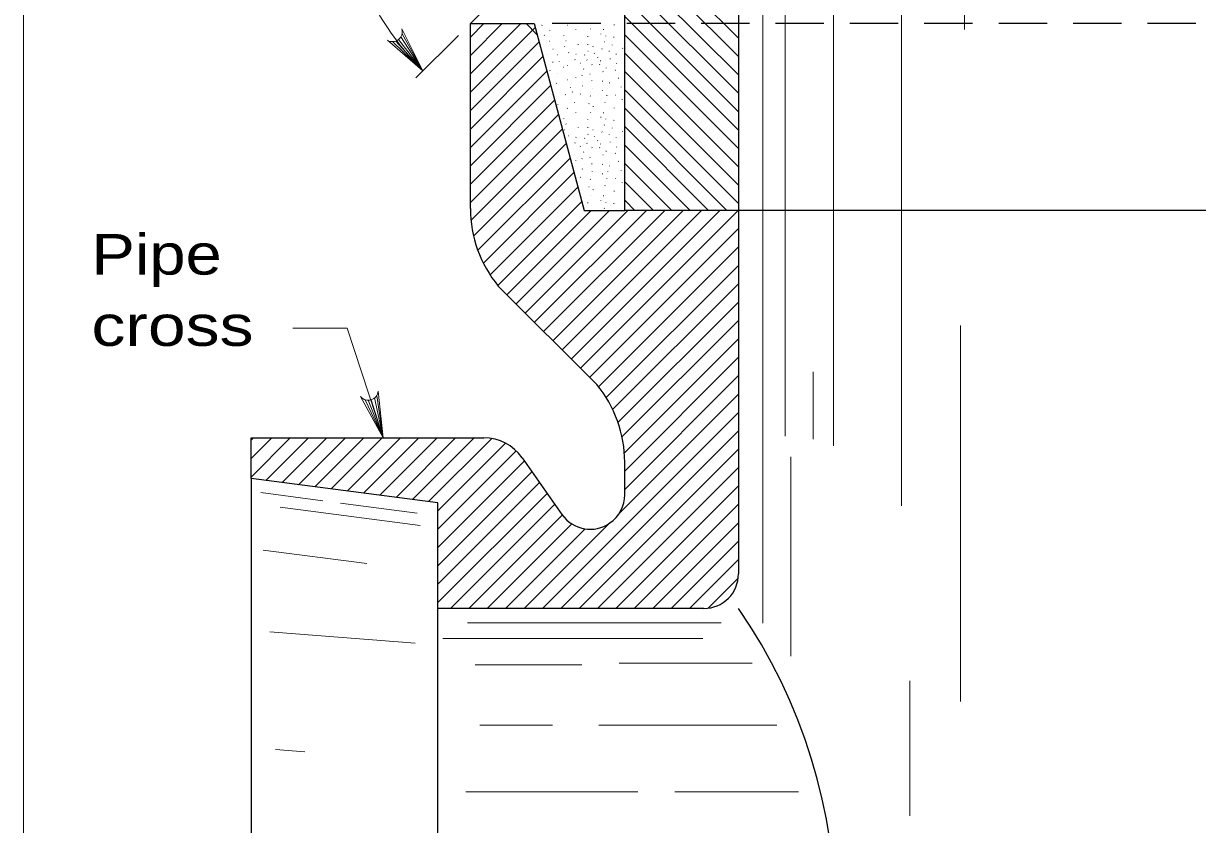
# Model space of a CAD drawing. Extents: x 1302.9 to 1336.9, y 688.5 to 710.5.
# Drawn here: x 1314.494 to 1319.007, y 697.687 to 700.767 of the extents above; entities that cross this region are included whole.
import ezdxf

# ---------------------------------------------------------------- set-up
doc = ezdxf.new("R2010")
doc.units = 0
doc.header["$LTSCALE"] = 0.062
doc.linetypes.add('MEDIUM_DASHED', pattern=[4.5, 3, -1.5])
doc.layers.add('1', color=7, linetype='Continuous', lineweight=13)

msp = doc.modelspace()

# ---------------------------------------------------------------- linework, layer by layer
at = {"layer": '1'}
for p, q in [((1314.49383, 700.27), (1314.49383, 706.63708)), ((1317.33667, 698.46067), (1317.33667, 702.85392)), ((1317.60758, 699.14283), (1317.60758, 702.36408)), ((1317.42233, 702.01592), (1317.42233, 699.18083)), ((1318.11208, 701.78092), (1318.11208, 700.74375)), ((1317.24267, 700.71042), (1316.80542, 701.14767)), ((1317.86967, 698.91258), (1317.86967, 701.1255)), ((1317.24267, 700.63975), (1316.80542, 701.077)), ((1317.24267, 700.56908), (1316.80542, 701.00633)), ((1317.24267, 700.49842), (1316.80542, 700.93567)), ((1317.24267, 700.42775), (1316.80542, 700.865)), ((1317.24267, 700.35708), (1316.80542, 700.79433)), ((1316.21192, 700.71442), (1316.26408, 700.76658)), ((1316.21192, 700.64375), (1316.33475, 700.76658)), ((1316.21192, 700.57308), (1316.40542, 700.76658)), ((1316.21192, 700.50242), (1316.46075, 700.75125)), ((1316.46792, 700.7245), (1316.42583, 700.76658)), ((1316.46792, 700.7245), (1316.42583, 700.76658)), ((1316.48725, 700.75908), (1316.48817, 700.75992)), ((1316.58375, 700.76092), (1316.5855, 700.7605)), ((1316.61675, 700.74367), (1316.61758, 700.7445)), ((1316.67317, 700.74492), (1316.674, 700.74575)), ((1316.723, 700.74383), (1316.72475, 700.7435)), ((1316.765, 700.761), (1316.7645, 700.76267)), ((1315.91342, 700.69692), (1316.02975, 700.5845)), ((1315.9255, 700.6995), (1316.02975, 700.5845)), ((1315.9355, 700.70517), (1316.02975, 700.5845)), ((1315.94508, 700.71625), (1316.02975, 700.5845)), ((1315.9495, 700.7275), (1316.02975, 700.5845)), ((1316.16608, 700.72075), (1316.00283, 700.5575)), ((1316.21192, 700.43175), (1316.47575, 700.69558)), ((1316.49633, 700.72075), (1316.49575, 700.72242)), ((1316.5155, 700.69908), (1316.51725, 700.69867)), ((1316.518, 700.73858), (1316.51742, 700.74025)), ((1316.5715, 700.72075), (1316.57092, 700.72242)), ((1316.57833, 700.7005), (1316.58008, 700.70017)), ((1316.66383, 700.71608), (1316.66317, 700.71775)), ((1316.71383, 700.72567), (1316.71325, 700.72733)), ((1316.72658, 700.69575), (1316.72742, 700.6965)), ((1316.73325, 700.71842), (1316.73267, 700.72008)), ((1316.76258, 700.71442), (1316.76425, 700.71408)), ((1317.24267, 700.28642), (1316.80542, 700.72367)), ((1316.52908, 700.66767), (1316.52992, 700.6685)), ((1316.57217, 700.67817), (1316.57383, 700.67783)), ((1316.58908, 700.65433), (1316.58992, 700.65517)), ((1316.62658, 700.68525), (1316.626, 700.68692)), ((1316.66283, 700.68667), (1316.6645, 700.68633)), ((1316.664, 700.66017), (1316.66483, 700.661)), ((1316.68317, 700.67767), (1316.684, 700.67842)), ((1316.68817, 700.65183), (1316.689, 700.65267)), ((1316.7185, 700.6685), (1316.71792, 700.67017)), ((1316.74567, 700.65975), (1316.74508, 700.66142)), ((1316.75725, 700.68367), (1316.75675, 700.68533)), ((1316.79708, 700.671), (1316.79792, 700.67183)), ((1317.24267, 700.21575), (1316.80542, 700.653)), ((1316.21192, 700.36108), (1316.49058, 700.63975)), ((1316.50908, 700.6485), (1316.50992, 700.64933)), ((1316.52883, 700.6175), (1316.52833, 700.61917)), ((1316.54575, 700.64683), (1316.54742, 700.646)), ((1316.55367, 700.61925), (1316.55308, 700.62092)), ((1316.5855, 700.60508), (1316.58492, 700.60675)), ((1316.61417, 700.627), (1316.61358, 700.62867)), ((1316.61742, 700.6485), (1316.61825, 700.64933)), ((1316.63458, 700.61408), (1316.63542, 700.61492)), ((1316.65075, 700.64517), (1316.65158, 700.646)), ((1316.66067, 700.6255), (1316.66008, 700.62717)), ((1316.68, 700.60817), (1316.67942, 700.60983)), ((1316.7015, 700.6365), (1316.70117, 700.63608)), ((1316.70217, 700.63683), (1316.7015, 700.6365)), ((1316.70917, 700.60842), (1316.70858, 700.61008)), ((1316.71225, 700.62242), (1316.71175, 700.62408)), ((1316.7495, 700.63008), (1316.74892, 700.63175)), ((1316.77275, 700.64808), (1316.77225, 700.64975)), ((1316.77308, 700.61175), (1316.77392, 700.61258)), ((1316.21192, 700.29042), (1316.50558, 700.584)), ((1316.51708, 700.58567), (1316.51883, 700.58525)), ((1316.54775, 700.57308), (1316.54858, 700.57392)), ((1316.56867, 700.59858), (1316.5695, 700.59942)), ((1316.61725, 700.55867), (1316.61675, 700.56033)), ((1316.64083, 700.56683), (1316.64167, 700.56767)), ((1316.6475, 700.59117), (1316.64692, 700.59283)), ((1316.671, 700.5715), (1316.67183, 700.57233)), ((1316.72067, 700.58175), (1316.72242, 700.58142)), ((1316.734, 700.59508), (1316.73342, 700.59667)), ((1316.76967, 700.5865), (1316.76917, 700.58817)), ((1317.24267, 700.14508), (1316.80542, 700.58233)), ((1316.21192, 700.21975), (1316.5205, 700.52833)), ((1316.54283, 700.53558), (1316.54225, 700.53725)), ((1316.58425, 700.54983), (1316.58508, 700.55075)), ((1316.59708, 700.52083), (1316.59658, 700.5225)), ((1316.64158, 700.52675), (1316.64242, 700.52758)), ((1316.67925, 700.54642), (1316.67867, 700.54808)), ((1316.67983, 700.5165), (1316.68067, 700.51733)), ((1316.71908, 700.5455), (1316.72083, 700.54508)), ((1316.73975, 700.51667), (1316.74058, 700.5175)), ((1316.74717, 700.53783), (1316.74667, 700.5395)), ((1316.78042, 700.557), (1316.78208, 700.55667)), ((1316.79217, 700.52158), (1316.79158, 700.52325)), ((1316.21192, 700.14908), (1316.53542, 700.47258)), ((1316.5765, 700.49267), (1316.57733, 700.4935)), ((1316.60317, 700.50375), (1316.60483, 700.50333)), ((1316.63458, 700.495), (1316.63542, 700.49583)), ((1316.67233, 700.48825), (1316.674, 700.48742)), ((1316.72, 700.50792), (1316.7195, 700.50958)), ((1316.73708, 700.48917), (1316.73658, 700.49083)), ((1316.768, 700.49133), (1316.76967, 700.491)), ((1316.79608, 700.47367), (1316.7955, 700.47533)), ((1317.24267, 700.07442), (1316.80542, 700.51167)), ((1316.54825, 700.45508), (1316.54767, 700.45675)), ((1316.58375, 700.44108), (1316.5855, 700.44067)), ((1316.61258, 700.46125), (1316.61208, 700.46292)), ((1316.61675, 700.42383), (1316.61758, 700.42467)), ((1316.66733, 700.45833), (1316.66817, 700.45917)), ((1316.67317, 700.42508), (1316.674, 700.42592)), ((1316.68317, 700.44833), (1316.68483, 700.4475)), ((1316.72883, 700.4625), (1316.72967, 700.46333)), ((1316.765, 700.44117), (1316.7645, 700.44283)), ((1317.19808, 700.04825), (1316.80542, 700.44092)), ((1316.21192, 700.07842), (1316.55042, 700.41683)), ((1316.5715, 700.401), (1316.57092, 700.40267)), ((1316.57833, 700.38075), (1316.58008, 700.38042)), ((1316.66383, 700.39633), (1316.66317, 700.398)), ((1316.71383, 700.40592), (1316.71325, 700.40758)), ((1316.723, 700.424), (1316.72475, 700.42367)), ((1316.73325, 700.39867), (1316.73267, 700.40033)), ((1316.76258, 700.39467), (1316.76425, 700.39433)), ((1316.21458, 700.01042), (1316.56533, 700.36117)), ((1316.57217, 700.35833), (1316.57383, 700.358)), ((1316.58908, 700.3345), (1316.58992, 700.33533)), ((1316.62658, 700.36542), (1316.626, 700.36708)), ((1316.66283, 700.36683), (1316.6645, 700.3665)), ((1316.664, 700.34033), (1316.66483, 700.34117)), ((1316.68317, 700.35783), (1316.684, 700.35858)), ((1316.7185, 700.34867), (1316.71792, 700.35033)), ((1316.72658, 700.37592), (1316.72742, 700.37675)), ((1316.74567, 700.33992), (1316.74508, 700.34158)), ((1316.75725, 700.36383), (1316.75675, 700.3655)), ((1316.79708, 700.35117), (1316.79792, 700.352)), ((1317.1275, 700.04825), (1316.80542, 700.37033)), ((1316.22417, 699.94933), (1316.58025, 700.30533)), ((1316.61417, 700.30717), (1316.61358, 700.30883)), ((1316.61742, 700.32867), (1316.61825, 700.3295)), ((1316.63458, 700.29425), (1316.63542, 700.29508)), ((1316.65075, 700.32533), (1316.65158, 700.32617)), ((1316.66067, 700.30567), (1316.66008, 700.30733)), ((1316.68, 700.28833), (1316.67942, 700.29)), ((1316.68817, 700.332), (1316.689, 700.33283)), ((1316.7015, 700.31667), (1316.70117, 700.31625)), ((1316.70217, 700.317), (1316.7015, 700.31667)), ((1316.70917, 700.28858), (1316.70858, 700.29025)), ((1316.71225, 700.30258), (1316.71175, 700.30425)), ((1316.7495, 700.31025), (1316.74892, 700.31192)), ((1316.77275, 700.32825), (1316.77225, 700.32992)), ((1316.77308, 700.29192), (1316.77392, 700.29275)), ((1317.05675, 700.04825), (1316.80542, 700.29958)), ((1314.49383, 696.11292), (1314.49383, 700.27)), ((1316.24075, 699.89517), (1316.59525, 700.24967)), ((1316.64083, 700.24708), (1316.64167, 700.24792)), ((1316.6475, 700.27133), (1316.64692, 700.273)), ((1316.671, 700.25175), (1316.67183, 700.25258)), ((1316.72067, 700.262), (1316.72242, 700.26158)), ((1316.734, 700.27525), (1316.73342, 700.27683)), ((1316.76967, 700.26667), (1316.76917, 700.26833)), ((1316.61725, 700.23892), (1316.61675, 700.24058)), ((1316.64158, 700.20692), (1316.64242, 700.20775)), ((1316.67925, 700.22658), (1316.67867, 700.22825)), ((1316.71908, 700.22567), (1316.72083, 700.22525)), ((1316.74717, 700.218), (1316.74667, 700.21967)), ((1316.78042, 700.23725), (1316.78208, 700.23692)), ((1316.79217, 700.20175), (1316.79158, 700.20342)), ((1316.98617, 700.04825), (1316.80542, 700.229)), ((1316.26208, 699.84583), (1316.61017, 700.19392)), ((1316.63458, 700.17517), (1316.63542, 700.176)), ((1316.67233, 700.16842), (1316.674, 700.16758)), ((1316.67983, 700.19667), (1316.68067, 700.1975)), ((1316.72, 700.18808), (1316.7195, 700.18975)), ((1316.73708, 700.16933), (1316.73658, 700.171)), ((1316.73975, 700.19683), (1316.74058, 700.19767)), ((1316.768, 700.1715), (1316.76967, 700.17117)), ((1316.79608, 700.15383), (1316.7955, 700.1555)), ((1316.91542, 700.04825), (1316.80542, 700.15825)), ((1316.28775, 699.80092), (1316.62517, 700.13817)), ((1316.66733, 700.1385), (1316.66817, 700.13933)), ((1316.68317, 700.1285), (1316.68483, 700.12767)), ((1316.72883, 700.14267), (1316.72967, 700.1435)), ((1316.765, 700.12133), (1316.7645, 700.123)), ((1316.31733, 699.75983), (1316.64008, 700.0825)), ((1316.66383, 700.0765), (1316.66317, 700.07817)), ((1316.67317, 700.10533), (1316.674, 700.10617)), ((1316.71383, 700.08608), (1316.71325, 700.08775)), ((1316.723, 700.10425), (1316.72475, 700.10392)), ((1316.73325, 700.07883), (1316.73267, 700.0805)), ((1316.76258, 700.07483), (1316.76425, 700.0745)), ((1316.84475, 700.04825), (1316.80542, 700.08767)), ((1316.35233, 699.72408), (1316.6765, 700.04825)), ((1316.38767, 699.68875), (1316.74717, 700.04825)), ((1316.423, 699.6535), (1316.81792, 700.04825)), ((1316.45833, 699.61808), (1316.8885, 700.04825)), ((1316.49367, 699.58275), (1316.95925, 700.04825)), ((1316.529, 699.54742), (1317.02983, 700.04825)), ((1316.56433, 699.51208), (1317.10058, 700.04825)), ((1316.59967, 699.47675), (1317.17125, 700.04825)), ((1316.63508, 699.44142), (1317.24192, 700.04825)), ((1316.72658, 700.05608), (1316.72742, 700.05692)), ((1316.80542, 700.04825), (1317.24267, 700.04825)), ((1316.67033, 699.40608), (1317.24267, 699.97833)), ((1316.70475, 699.36983), (1317.24267, 699.90767)), ((1316.73392, 699.32833), (1317.24267, 699.837)), ((1316.75892, 699.28258), (1317.24267, 699.76633)), ((1316.77933, 699.23233), (1317.24267, 699.69567)), ((1316.79475, 699.17708), (1317.24267, 699.625)), ((1318.09675, 698.1605), (1318.09675, 699.6055)), ((1316.80358, 699.11525), (1317.24267, 699.55433)), ((1316.80525, 699.04625), (1317.24267, 699.48367)), ((1316.80525, 698.9755), (1317.24267, 699.41292)), ((1317.52975, 699.42767), (1317.52975, 699.16825)), ((1316.78383, 698.8835), (1317.24267, 699.34233)), ((1315.80742, 699.32008), (1315.87642, 699.17375)), ((1315.81958, 699.31825), (1315.87642, 699.17375)), ((1315.83092, 699.32), (1315.87642, 699.17375)), ((1315.84383, 699.327), (1315.87642, 699.17375)), ((1315.85192, 699.33592), (1315.87642, 699.17375)), ((1316.48883, 698.51792), (1317.24267, 699.27158)), ((1315.36858, 699.1645), (1315.37783, 699.17375)), ((1315.36858, 699.09383), (1315.4485, 699.17375)), ((1315.36858, 699.02317), (1315.51917, 699.17375)), ((1315.42617, 699.01008), (1315.58992, 699.17375)), ((1315.48867, 699.00192), (1315.66058, 699.17375)), ((1315.55125, 698.99375), (1315.73125, 699.17375)), ((1315.61375, 698.98558), (1315.80192, 699.17375)), ((1315.67625, 698.97742), (1315.87258, 699.17375)), ((1315.73883, 698.96925), (1315.94333, 699.17375)), ((1315.80125, 698.96117), (1316.01392, 699.17375)), ((1315.86383, 698.953), (1316.08467, 699.17375)), ((1315.92642, 698.94492), (1316.15525, 699.17375)), ((1315.98883, 698.93675), (1316.226, 699.17375)), ((1316.05142, 698.92858), (1316.294, 699.17108)), ((1316.5595, 698.51792), (1317.24267, 699.201)), ((1316.087, 698.89342), (1316.34675, 699.15317)), ((1316.087, 698.82275), (1316.388, 699.12375)), ((1316.63025, 698.51792), (1317.24267, 699.13025)), ((1316.087, 698.75208), (1316.41975, 699.08483)), ((1317.44425, 699.10142), (1317.44425, 698.33425)), ((1316.087, 698.68142), (1316.44883, 699.04325)), ((1316.70083, 698.51792), (1317.24267, 699.05967)), ((1316.087, 698.61075), (1316.478, 699.00167)), ((1316.77158, 698.51792), (1317.24267, 698.98892)), ((1315.64492, 698.93217), (1315.406, 698.96325)), ((1316.087, 698.54008), (1316.507, 698.96017)), ((1316.01933, 698.8365), (1315.48058, 698.90683)), ((1316.00725, 698.88483), (1315.71283, 698.92325)), ((1316.13542, 698.51792), (1316.53617, 698.91858)), ((1316.84217, 698.51792), (1317.24267, 698.91833)), ((1316.20608, 698.51792), (1316.56542, 698.87708)), ((1316.91292, 698.51792), (1317.24267, 698.84758)), ((1316.27683, 698.51792), (1316.60208, 698.84308)), ((1316.3475, 698.51792), (1316.65383, 698.82417)), ((1316.41817, 698.51792), (1316.74392, 698.84358)), ((1316.98358, 698.51792), (1317.24267, 698.777)), ((1315.81392, 698.69033), (1315.41492, 698.74242)), ((1317.05425, 698.51792), (1317.24267, 698.70625)), ((1317.12642, 698.51942), (1317.24125, 698.63417)), ((1317.1765, 698.46217), (1316.20075, 698.46217)), ((1315.99958, 698.384), (1315.44033, 698.42817)), ((1317.10508, 698.40258), (1316.10558, 698.40258)), ((1317.2955, 698.30725), (1316.78383, 698.30725)), ((1316.641, 698.30133), (1316.2305, 698.30133)), ((1317.9015, 697.72075), (1317.9015, 698.2395)), ((1316.52792, 698.069), (1316.24833, 698.069)), ((1317.39067, 698.069), (1316.70642, 698.069)), ((1315.57542, 697.966), (1315.46233, 697.97575)), ((1316.85517, 697.81275), (1316.19475, 697.81275)), ((1317.474, 697.81275), (1316.998, 697.81275))]:
    msp.add_line(p, q, dxfattribs=at)
at = {"layer": '1', "lineweight": 25}
for p, q in [((1316.80542, 700.04825), (1316.80542, 703.0465)), ((1316.80542, 701.36), (1316.21192, 700.76658)), ((1317.24267, 700.04825), (1317.24267, 698.65067)), ((1321.64692, 700.04825), (1317.24267, 700.04825)), ((1316.69775, 699.37875), (1316.31933, 699.75708)), ((1316.41092, 699.09742), (1316.56383, 698.879)), ((1316.80525, 698.95525), (1316.80525, 699.08017)), ((1315.36858, 699.01758), (1315.36858, 695.61325)), ((1317.10992, 698.51792), (1316.087, 698.51792))]:
    msp.add_line(p, q, dxfattribs=at)
at = {"layer": '1', "linetype": 'MEDIUM_DASHED', "lineweight": 25}
msp.add_line((1322.433, 700.76658), (1316.45667, 700.76658), dxfattribs=at)
at = {"layer": '1', "lineweight": 25}
for points in [[(1317.24267, 703.06167), (1317.24267, 700.04825), (1316.80542, 700.04825)], [(1316.21192, 700.05567), (1316.21192, 700.76658), (1316.45667, 700.76658), (1316.64925, 700.04825), (1316.80542, 700.04825)], [(1316.087, 695.70692), (1316.087, 698.92392), (1315.36858, 699.01758), (1315.36858, 699.17375), (1316.26425, 699.17375)]]:
    msp.add_lwpolyline(points, dxfattribs=at)
at = {"layer": '1'}
for points in [[(1315.94867, 700.74575), (1316.02975, 700.5845), (1315.89292, 700.70217)], [(1315.87642, 699.17375), (1315.73842, 699.59608), (1315.52917, 699.59608)], [(1315.85767, 699.35325), (1315.87642, 699.17375), (1315.79008, 699.33225)]]:
    msp.add_lwpolyline(points, dxfattribs=at)
for centre, radius, start, end in [((1316.80539, 701.35999), 1.09683, 179.99836, 224.99685), ((1315.91196, 700.73517), 0.0382, 240.09342, 15.91955), ((1315.81957, 699.3564), 0.0382, 219.36471, 355.19083)]:
    msp.add_arc(centre, radius, start, end, dxfattribs=at)
at = {"layer": '1', "lineweight": 25}
for centre, major_axis, start_param, end_param in [((1316.68045, 700.05566), (0.46853, 0), 3.1415927, 3.8325697), ((1316.3367, 699.08014), (-0.46853, 0), 3.1415927, 3.8325697), ((1316.26421, 698.99468), (-0.17909, 0), 3.7523998, 4.7122583), ((1316.67251, 698.95518), (0.13275, 0), 5.3232961, 6.2834344), ((1316.67256, 698.95515), (0.13275, 0), 3.7524998, 5.3232961), ((1317.10994, 698.65061), (-0.13275, 0), 1.5707963, 3.1415927), ((1315.50086, 697.31541), (2.11665, 0), 5.6789145, 6.8874561)]:
    msp.add_ellipse(centre, major_axis=major_axis, ratio=0.999895, start_param=start_param, end_param=end_param, dxfattribs=at)

# ---------------------------------------------------------------- texts
at = {"layer": '1'}
for s, width, p in [('Pipe', 1.2, (1314.75517, 699.80142)), ('cross', 1.25, (1314.75517, 699.52742))]:
    msp.add_text(s, height=0.156, dxfattribs=dict(at, width=width)).set_placement(p)

doc.saveas('drawing.dxf')
